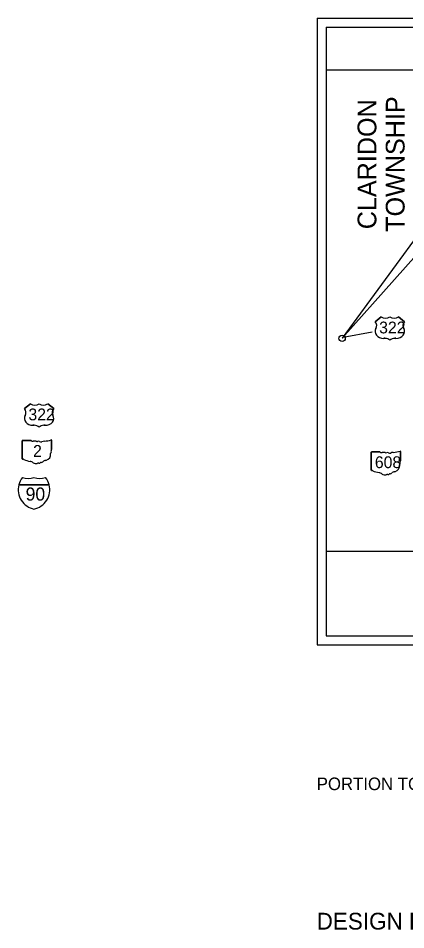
# Model space of a CAD drawing. Extents: x -17.5 to 72.9, y -57.8 to 32.3.
# Drawn here: x 38.3 to 42.62, y -47.51 to -37.33 of the extents above; entities that cross this region are included whole.
import ezdxf

# ---------------------------------------------------------------- set-up
doc = ezdxf.new("R2010")
doc.units = 0
for name, color, linetype in [('GM_X_Interstate_Shield', 7, 'Continuous'), ('GM_X_Township', 7, 'Continuous'), ('SH_Data', 7, 'Continuous'), ('SH_Text', 7, 'Continuous')]:
    doc.layers.add(name, color=color, linetype=linetype)

msp = doc.modelspace()

# ---------------------------------------------------------------- linework, layer by layer
at = {"layer": 'GM_X_Interstate_Shield'}
for p, q in [((38.304, -42.543), (38.642, -42.543)), ((38.642, -42.543), (38.304, -42.543)), ((38.642, -42.543), (38.304, -42.543))]:
    msp.add_line(p, q, dxfattribs=at)
for centre, start, end in [((38.517, -42.597), 141.669, 165.8066), ((38.409, -42.251), 253.0091, 286.9909), ((38.537, -42.251), 253.0091, 286.9909), ((38.429, -42.597), 14.1934, 38.331), ((38.517, -42.597), 165.8066, 258.463), ((38.429, -42.597), 281.537, 14.1934)]:
    msp.add_arc(centre, 0.22, start, end, dxfattribs=at)
at = {"layer": 'GM_X_Township'}
for p, q in [((48.536, -37.898), (41.736, -37.91)), ((48.536, -43.276), (41.736, -43.288))]:
    msp.add_line(p, q, dxfattribs=at)
at = {"layer": 'SH_Data'}
for p, q in [((41.636, -37.329), (48.636, -37.329)), ((41.636, -37.329), (41.636, -44.329)), ((41.736, -37.429), (41.736, -44.229)), ((41.736, -37.429), (48.536, -37.429)), ((42.352, -40.665), (42.283, -40.72)), ((42.283, -40.72), (42.352, -40.665)), ((42.611, -40.72), (42.543, -40.665)), ((42.543, -40.665), (42.611, -40.72)), ((41.925, -40.892), (42.25, -40.834)), ((42.379, -40.905), (42.393, -40.905)), ((42.393, -40.905), (42.379, -40.905)), ((42.502, -40.905), (42.515, -40.905)), ((42.515, -40.905), (42.502, -40.905)), ((38.435, -41.636), (38.366, -41.69)), ((38.366, -41.69), (38.435, -41.636)), ((38.694, -41.69), (38.626, -41.636)), ((38.626, -41.636), (38.694, -41.69)), ((38.462, -41.876), (38.475, -41.876)), ((38.475, -41.876), (38.462, -41.876)), ((38.585, -41.876), (38.598, -41.876)), ((38.598, -41.876), (38.585, -41.876)), ((38.341, -42.051), (38.341, -42.251)), ((38.341, -42.251), (38.341, -42.051)), ((38.441, -42.047), (38.344, -42.047)), ((38.344, -42.047), (38.441, -42.047)), ((38.67, -42.147), (38.67, -42.042)), ((38.67, -42.042), (38.67, -42.147)), ((38.67, -42.147), (38.67, -42.147)), ((38.67, -42.147), (38.67, -42.147)), ((42.238, -42.178), (42.238, -42.378)), ((42.238, -42.378), (42.238, -42.178)), ((42.337, -42.174), (42.241, -42.174)), ((42.241, -42.174), (42.337, -42.174)), ((42.567, -42.274), (42.567, -42.169)), ((42.567, -42.169), (42.567, -42.274)), ((42.567, -42.274), (42.567, -42.274)), ((42.567, -42.274), (42.567, -42.274)), ((38.642, -42.543), (38.304, -42.543)), ((38.642, -42.543), (38.304, -42.543)), ((41.736, -44.229), (48.536, -44.229)), ((41.636, -44.329), (48.636, -44.329))]:
    msp.add_line(p, q, dxfattribs=at)
msp.add_lwpolyline([(42.875, -39.592), (41.914, -40.905), (43.083, -39.592)], close=True, dxfattribs=at)
msp.add_circle((41.914, -40.905), 0.0357, dxfattribs=at)
for centre, start, end in [((38.517, -42.597), 141.669, 165.8066), ((38.409, -42.251), 253.0091, 286.9909), ((38.537, -42.251), 253.0091, 286.9909), ((38.429, -42.597), 14.1934, 38.331), ((38.517, -42.597), 165.8066, 258.463), ((38.429, -42.597), 281.537, 14.1934)]:
    msp.add_arc(centre, 0.22, start, end, dxfattribs=at)
for centre, major_axis, start_param, end_param in [((42.205, -40.763), (0.0955, 0), 5.838949, 6.894067), ((42.205, -40.763), (0.0955, 0), 5.838949, 6.894067), ((42.399, -40.626), (-0.0682, 0), 0.795399, 2.346194), ((42.399, -40.626), (-0.0682, 0), 0.795399, 2.346194), ((42.495, -40.626), (-0.0682, 0), 0.795399, 2.346194), ((42.495, -40.626), (-0.0682, 0), 0.795399, 2.346194), ((42.689, -40.763), (-0.0955, 0), 5.672304, 6.727422), ((42.689, -40.763), (-0.0955, 0), 5.672304, 6.727422), ((42.378, -40.829), (0.0955, 0), 2.702327, 4.723529), ((42.378, -40.829), (0.0955, 0), 2.702327, 4.723529), ((42.516, -40.829), (-0.0955, 0), 1.559657, 3.580859), ((42.516, -40.829), (-0.0955, 0), 1.559657, 3.580859), ((42.393, -40.96), (-0.0682, 0), 3.785094, 4.712389), ((42.393, -40.96), (-0.0682, 0), 3.785094, 4.712389), ((42.502, -40.96), (-0.0682, 0), 4.712389, 5.639684), ((42.502, -40.96), (-0.0682, 0), 4.712389, 5.639684), ((38.482, -41.597), (-0.0682, 0), 0.795399, 2.346194), ((38.482, -41.597), (-0.0682, 0), 0.795399, 2.346194), ((38.578, -41.597), (-0.0682, 0), 0.795399, 2.346194), ((38.578, -41.597), (-0.0682, 0), 0.795399, 2.346194), ((38.288, -41.734), (0.0955, 0), 5.838949, 6.894067), ((38.288, -41.734), (0.0955, 0), 5.838949, 6.894067), ((38.772, -41.734), (-0.0955, 0), 5.672304, 6.727422), ((38.772, -41.734), (-0.0955, 0), 5.672304, 6.727422), ((38.461, -41.8), (0.0955, 0), 2.702327, 4.723529), ((38.461, -41.8), (0.0955, 0), 2.702327, 4.723529), ((38.599, -41.8), (-0.0955, 0), 1.559657, 3.580859), ((38.599, -41.8), (-0.0955, 0), 1.559657, 3.580859), ((38.475, -41.931), (-0.0682, 0), 3.785094, 4.712389), ((38.475, -41.931), (-0.0682, 0), 3.785094, 4.712389), ((38.585, -41.931), (-0.0682, 0), 4.712389, 5.639684), ((38.585, -41.931), (-0.0682, 0), 4.712389, 5.639684), ((38.345, -42.05), (0.00382, 0), 1.712693, 3.28349), ((38.345, -42.05), (0.00382, 0), 1.712693, 3.28349), ((38.464, -42.024), (0.037, 0), 4.042523, 4.731795), ((38.464, -42.024), (0.037, 0), 4.042523, 4.731795), ((38.476, -42.16), (0.133, 0), 1.404758, 1.657858), ((38.476, -42.16), (0.133, 0), 1.404758, 1.657858), ((38.506, -42.049), (0.0107, 0), 3.836095, 5.185415), ((38.506, -42.049), (0.0107, 0), 3.836095, 5.185415), ((38.522, -42.073), (0.0222, 0), 0.950623, 2.079405), ((38.522, -42.073), (0.0222, 0), 0.950623, 2.079405), ((38.598, -42.109), (0.0703, 0), 1.699011, 2.107814), ((38.598, -42.109), (0.0703, 0), 1.699011, 2.107814), ((38.553, -41.775), (0.35, 0), 4.814394, 5.042369), ((38.553, -41.775), (0.35, 0), 4.814394, 5.042369), ((38.667, -42.042), (0.00367, 0), 6.141152, 7.989035), ((38.667, -42.042), (0.00367, 0), 6.141152, 7.989035), ((38.55, -42.041), (0.0267, 0), 4.081561, 5.145723), ((38.55, -42.041), (0.0267, 0), 4.081561, 5.145723), ((38.67, -42.155), (0.00568, 0), 1.883978, 3.671073), ((38.67, -42.155), (0.00568, 0), 1.883978, 3.671073), ((38.633, -42.168), (0.0341, 0), 5.934695, 6.695948), ((38.633, -42.168), (0.0341, 0), 5.934695, 6.695948), ((38.666, -42.148), (0.00393, 0), 5.05454, 6.418171), ((38.666, -42.148), (0.00393, 0), 5.05454, 6.418171), ((38.345, -42.251), (0.00385, 0), 3.00124, 4.508301), ((38.345, -42.251), (0.00385, 0), 3.00124, 4.508301), ((38.345, -42.231), (0.0294, 0), 4.665946, 4.897461), ((38.345, -42.231), (0.0294, 0), 4.665946, 4.897461), ((38.351, -42.263), (0.0106, 0), 0.519207, 1.627899), ((38.351, -42.263), (0.0106, 0), 0.519207, 1.627899), ((38.485, -42.083), (0.252, 0), 4.195997, 4.488961), ((38.485, -42.083), (0.252, 0), 4.195997, 4.488961), ((38.573, -42.204), (0.0874, 0), 5.101752, 6.440018), ((38.573, -42.204), (0.0874, 0), 5.101752, 6.440018), ((38.684, -42.191), (0.0248, 0), 2.387724, 3.262537), ((38.684, -42.191), (0.0248, 0), 2.387724, 3.262537), ((42.241, -42.177), (0.00382, 0), 1.712693, 3.28349), ((42.241, -42.177), (0.00382, 0), 1.712693, 3.28349), ((42.36, -42.151), (0.037, 0), 4.042523, 4.731795), ((42.36, -42.151), (0.037, 0), 4.042523, 4.731795), ((42.373, -42.287), (0.133, 0), 1.404758, 1.657858), ((42.373, -42.287), (0.133, 0), 1.404758, 1.657858), ((42.403, -42.176), (0.0107, 0), 3.836095, 5.185415), ((42.403, -42.176), (0.0107, 0), 3.836095, 5.185415), ((42.419, -42.199), (0.0222, 0), 0.950623, 2.079405), ((42.419, -42.199), (0.0222, 0), 0.950623, 2.079405), ((42.447, -42.168), (0.0267, 0), 4.081561, 5.145723), ((42.447, -42.168), (0.0267, 0), 4.081561, 5.145723), ((42.494, -42.235), (0.0703, 0), 1.699011, 2.107814), ((42.494, -42.235), (0.0703, 0), 1.699011, 2.107814), ((42.45, -41.901), (0.35, 0), 4.814394, 5.042369), ((42.45, -41.901), (0.35, 0), 4.814394, 5.042369), ((42.564, -42.169), (0.00367, 0), 6.141152, 7.989035), ((42.564, -42.169), (0.00367, 0), 6.141152, 7.989035), ((38.41, -42.341), (0.079, 0), 0.823519, 1.323587), ((38.41, -42.341), (0.079, 0), 0.823519, 1.323587), ((38.495, -42.264), (0.0501, 0), 4.026481, 4.996735), ((38.495, -42.264), (0.0501, 0), 4.026481, 4.996735), ((38.524, -42.333), (0.0412, 0), 1.495662, 1.94098), ((38.524, -42.333), (0.0412, 0), 1.495662, 1.94098), ((38.528, -42.279), (0.0267, 0), 4.691044, 5.507374), ((38.528, -42.279), (0.0267, 0), 4.691044, 5.507374), ((38.552, -42.298), (0.00752, 0), 1.147584, 2.315152), ((38.552, -42.298), (0.00752, 0), 1.147584, 2.315152), ((38.549, -42.27), (0.0282, 0), 4.937069, 5.64225), ((38.549, -42.27), (0.0282, 0), 4.937069, 5.64225), ((38.609, -42.307), (0.0479, 0), 1.647645, 2.488434), ((38.609, -42.307), (0.0479, 0), 1.647645, 2.488434), ((42.469, -42.331), (0.0874, 0), 5.101752, 6.440018), ((42.469, -42.331), (0.0874, 0), 5.101752, 6.440018), ((42.58, -42.318), (0.0248, 0), 2.387724, 3.262537), ((42.58, -42.318), (0.0248, 0), 2.387724, 3.262537), ((42.566, -42.282), (0.00568, 0), 1.883978, 3.671073), ((42.566, -42.282), (0.00568, 0), 1.883978, 3.671073), ((42.53, -42.295), (0.0341, 0), 5.934695, 6.695948), ((42.53, -42.295), (0.0341, 0), 5.934695, 6.695948), ((42.563, -42.274), (0.00393, 0), 5.05454, 6.418171), ((42.563, -42.274), (0.00393, 0), 5.05454, 6.418171), ((42.241, -42.378), (0.00385, 0), 3.00124, 4.508301), ((42.241, -42.378), (0.00385, 0), 3.00124, 4.508301), ((42.242, -42.358), (0.0294, 0), 4.665946, 4.897461), ((42.242, -42.358), (0.0294, 0), 4.665946, 4.897461), ((42.248, -42.389), (0.0106, 0), 0.519207, 1.627899), ((42.248, -42.389), (0.0106, 0), 0.519207, 1.627899), ((42.382, -42.209), (0.252, 0), 4.195997, 4.488961), ((42.382, -42.209), (0.252, 0), 4.195997, 4.488961), ((42.307, -42.468), (0.079, 0), 0.823519, 1.323587), ((42.307, -42.468), (0.079, 0), 0.823519, 1.323587), ((42.392, -42.39), (0.0501, 0), 4.026481, 4.996735), ((42.392, -42.39), (0.0501, 0), 4.026481, 4.996735), ((42.421, -42.459), (0.0412, 0), 1.495662, 1.94098), ((42.421, -42.459), (0.0412, 0), 1.495662, 1.94098), ((42.425, -42.405), (0.0267, 0), 4.691044, 5.507374), ((42.425, -42.405), (0.0267, 0), 4.691044, 5.507374), ((42.449, -42.425), (0.00752, 0), 1.147584, 2.315152), ((42.449, -42.425), (0.00752, 0), 1.147584, 2.315152), ((42.446, -42.397), (0.0282, 0), 4.937069, 5.64225), ((42.446, -42.397), (0.0282, 0), 4.937069, 5.64225), ((42.506, -42.434), (0.0479, 0), 1.647645, 2.488434), ((42.506, -42.434), (0.0479, 0), 1.647645, 2.488434)]:
    msp.add_ellipse(centre, major_axis=major_axis, ratio=0.8, start_param=start_param, end_param=end_param, dxfattribs=at)

# ---------------------------------------------------------------- texts
at = {"layer": 'GM_X_Interstate_Shield'}
msp.add_text('90', height=0.1465, dxfattribs=at).set_placement((38.38, -42.718))
at = {"layer": 'SH_Data'}
for s, p in [('CLARIDON', (42.297, -39.686)), ('TOWNSHIP', (42.612, -39.715))]:
    msp.add_text(s, height=0.21, rotation=90, dxfattribs=at).set_placement(p)
for s, height, p in [('322', 0.1318, (42.328, -40.85)), ('322', 0.1318, (38.411, -41.821)), ('2', 0.132, (38.463, -42.229)), ('608', 0.1318, (42.28, -42.355)), ('DESIGN DESIGNATION', 0.1875, (41.63, -47.51))]:
    msp.add_text(s, height=height, dxfattribs=at).set_placement(p)
at = {"layer": 'SH_Text'}
msp.add_text('PORTION TO BE IMPROVED', height=0.14, dxfattribs=at).set_placement((41.631, -45.952))

doc.saveas('drawing.dxf')
